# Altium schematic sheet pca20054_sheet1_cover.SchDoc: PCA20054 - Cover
size A3; Organization: Nordic Semiconductor; DocumentNumber: 1; Revision: 1.0.0; SheetNumber: 1; SheetTotal: 5; Date: 2020-02-07; CompanyName: Nordic Semiconductor; DrawnBy: KJP; ProjectNumber: 4467
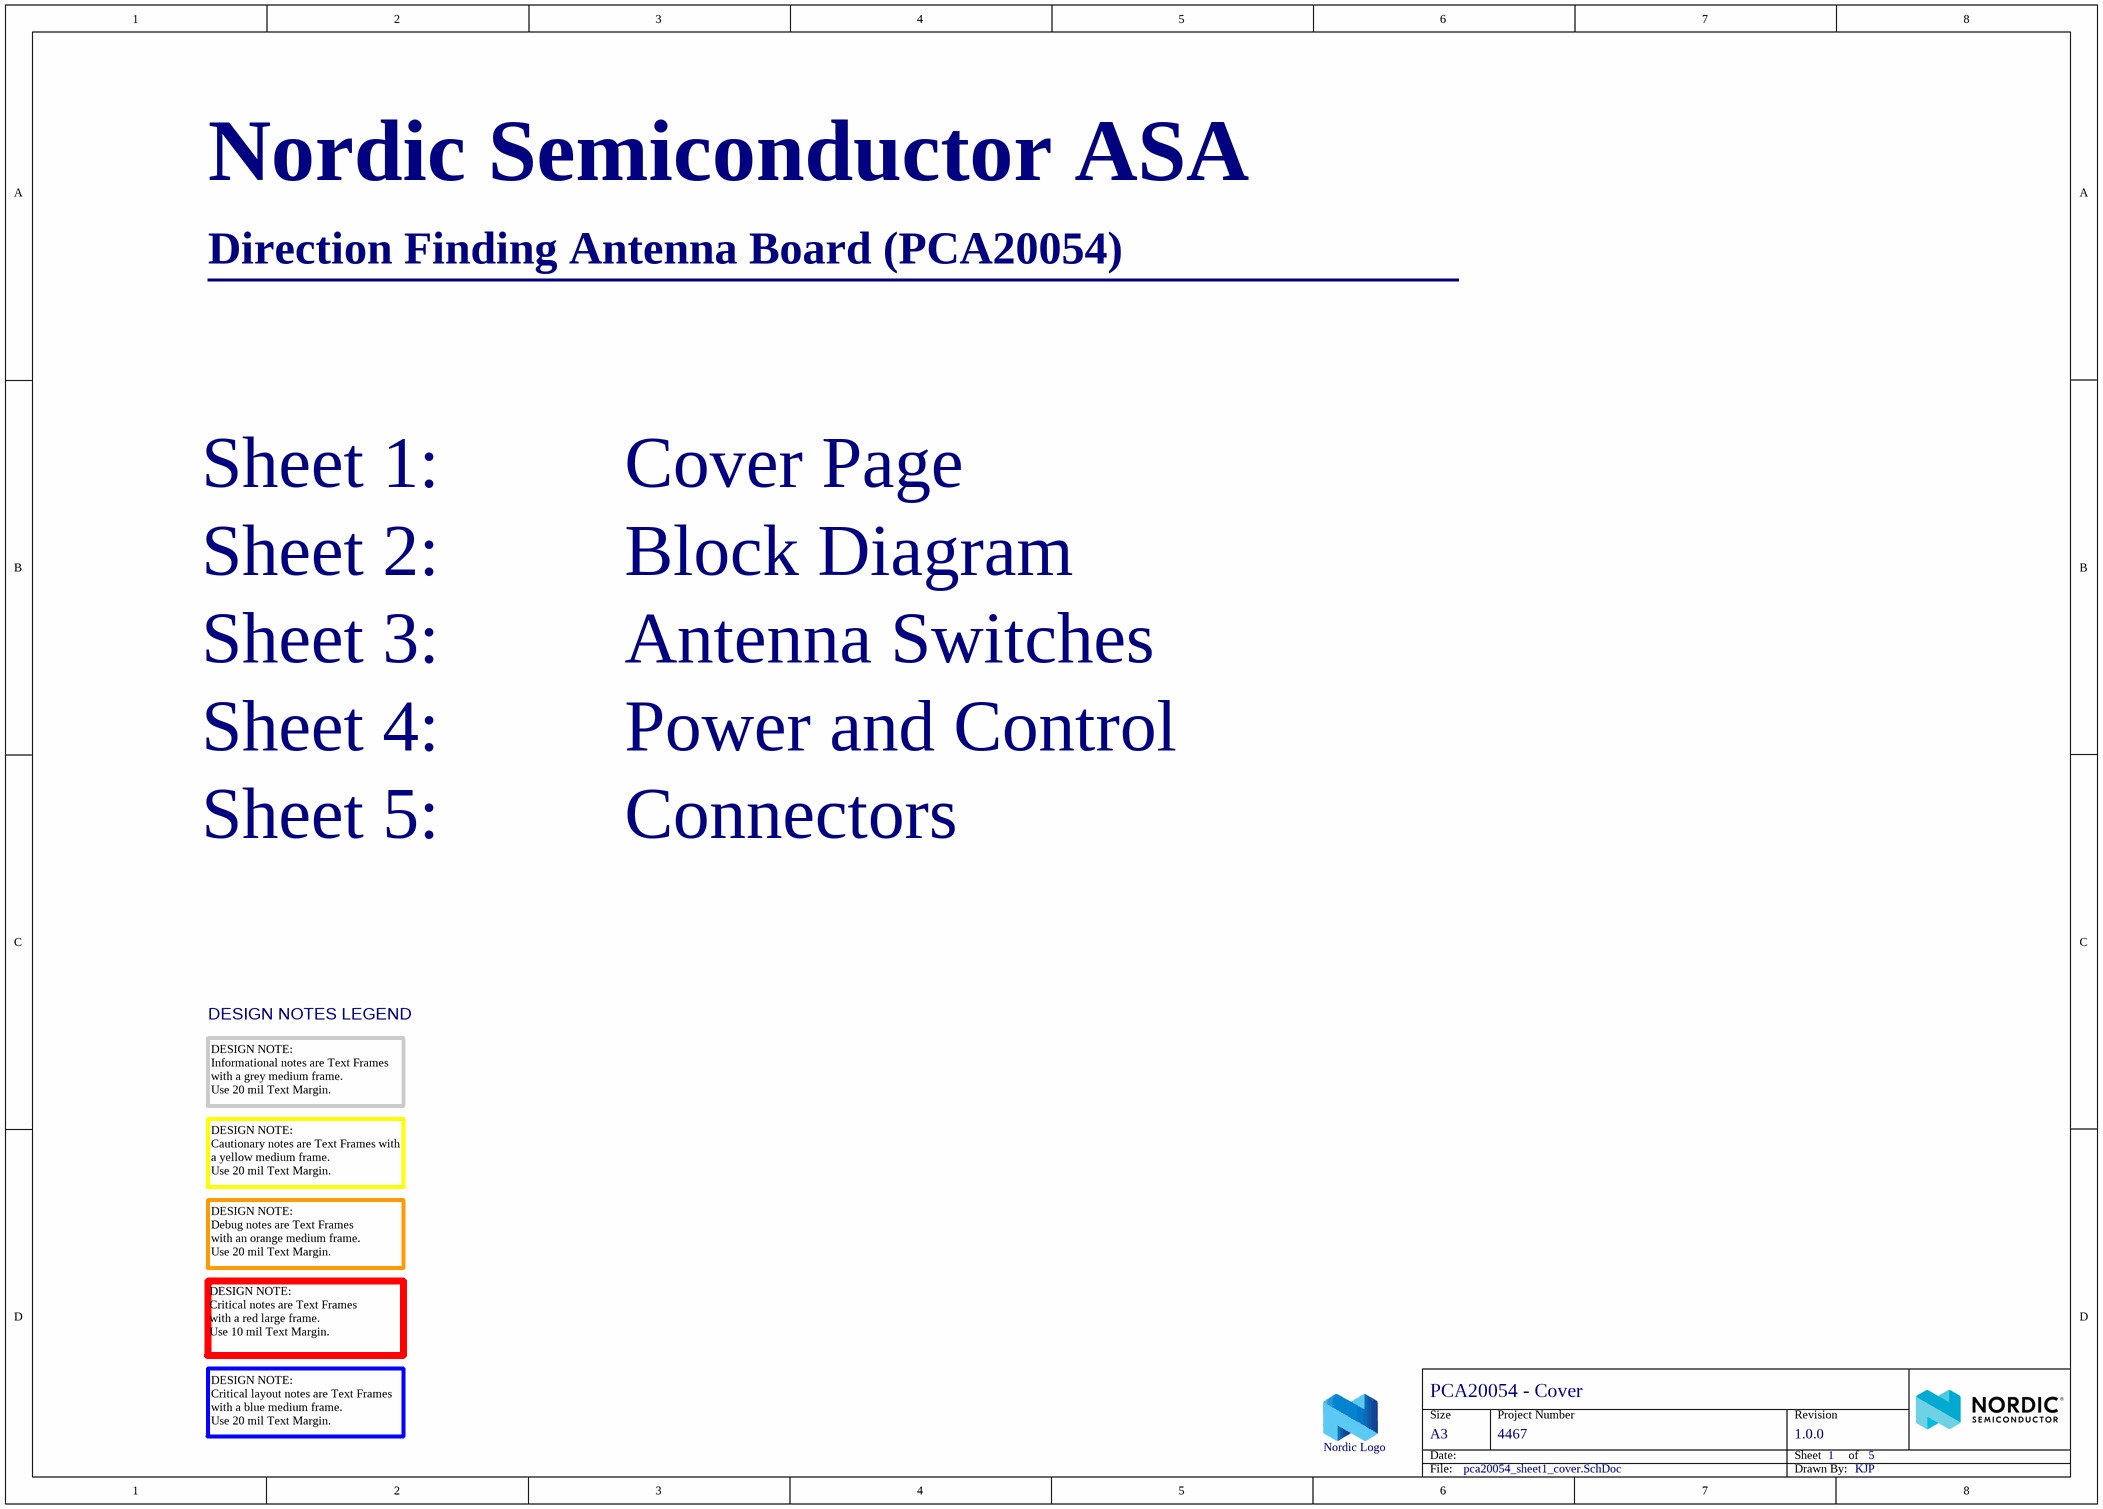
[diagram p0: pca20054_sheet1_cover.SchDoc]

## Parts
LOGO?  Nordic Logo  [NORDIC_LOGO_LYING]  (no BOM)

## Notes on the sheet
- Nordic Semiconductor ASA
- Direction Finding Antenna Board (PCA20054)
- _________________________________________
- Sheet 1:          Cover Page
- Sheet 2:          Block Diagram
- Sheet 3:          Antenna Switches
- Sheet 4:          Power and Control
- Sheet 5:          Connectors
- DESIGN NOTES LEGEND
- DESIGN NOTE:
  Informational notes are Text Frames with a grey medium frame.
  Use 20 mil Text Margin.
- DESIGN NOTE:
  Cautionary notes are Text Frames with a yellow medium frame.
  Use 20 mil Text Margin.
- DESIGN NOTE:
  Debug notes are Text Frames
  with an orange medium frame.
  Use 20 mil Text Margin.
- DESIGN NOTE:
  Critical notes are Text Frames
  with a red large frame.
  Use 10 mil Text Margin.
- DESIGN NOTE:
  Critical layout notes are Text Frames
  with a blue medium frame.
  Use 20 mil Text Margin.

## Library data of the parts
LOGO? = Nordic Logo lying: Artikkelnr Noca: N.A.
